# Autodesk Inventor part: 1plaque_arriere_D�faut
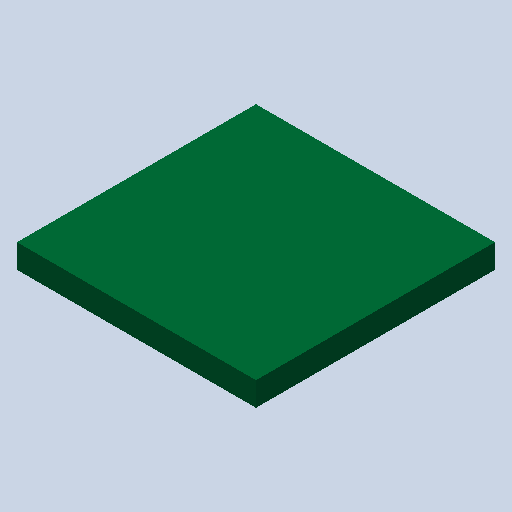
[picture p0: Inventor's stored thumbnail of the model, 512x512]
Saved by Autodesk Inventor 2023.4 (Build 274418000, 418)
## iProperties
Created: 2011-01
Part Number: 1plaque_arriere_D�faut
Document SubType Name: Modeling
Designer: eric
Density: 1 g/cm^3
Mass: 6.4 g
Surface Area: 38.4 cm^2
Volume: 6.4 cm^3
Material: Générique
Appearance: 0,128,64_1
Author: eric
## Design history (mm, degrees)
feature "Base1"
node "Corps solides"
node "Corps surfaciques"
node "Solide1"
